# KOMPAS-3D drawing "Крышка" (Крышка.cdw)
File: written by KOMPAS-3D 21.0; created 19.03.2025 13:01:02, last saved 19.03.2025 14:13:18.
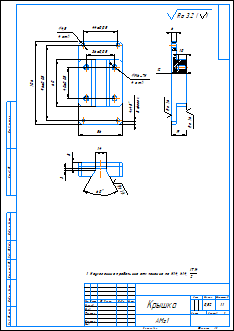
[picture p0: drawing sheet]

Sheet 1: A3, portrait

Document properties: Автор: User; Полное имя файла: C:\Users\User\Desktop\Ринат все\Ринат\Перспектива\чертежи\Крышка.cdw; Знак неуказанной шероховатости: 4; Параметр неуказанной шероховатости: Ra 3.2; Масса: 0.51788

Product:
- Part/product: Крышка
    Масса: 0.51788
  - Body: Тело 4
      Масса: 0.457319

Title block, sheet 1: Наименование: Крышка; Материал: АМг1; Масса: 0,52; Количество листов документа: 1; Форматы листов документа: A3

Views: Вид 1, Справа, Проекционный вид 4, Проекционный вид 5, Местный разрез 1, Местный разрез 2
Referenced files in C:\Users\User\Desktop\Ринат все\Ринат\Перспектива\: Крышка.m3d
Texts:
  Ra 1.6
  1. Неуказанные предельные отклонения по Н14, h14,  IT14 2
  Ra 3.2
  Ra 3.2 ( )
Dimensions and other numbers on the sheet: 106; 60; 40±0,05; 4; 8 фасок; 44±0,05; 96±0,05; 36±0,05; 56; 4,5; 4 отв.; 8; 3; 14; 6; 10; 12; 19; 1:1; 1; 0,52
